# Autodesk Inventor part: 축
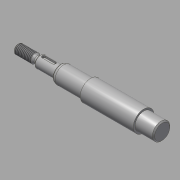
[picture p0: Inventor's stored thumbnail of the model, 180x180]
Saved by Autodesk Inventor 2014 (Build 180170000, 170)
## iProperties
Created: 2015-11
Part Number: 축
Material: 강철, 연강
Document SubType Name: Modeling
Designer: mduedu
Density: 1 g/cm^3
Appearance: 강철
Author: mduedu
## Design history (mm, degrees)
sketch "스케치1"
  geometry: L1 (-86, 0)-(86, 0); L2 (-86, 0)-(-86, 4); L3 (-86, 4)-(-70.732, 4); L4 (-70.732, 4)-(-69, 3); L5 (-69, 3)-(-67, 3); L6 (-67, 3)-(-67, 5); L7 (-67, 5)-(-49, 5); L8 (-49, 5)-(-49, 6.55); L9 (-47.355, 7.5)-(-23, 7.5); L10 (-23, 7.5)-(-23, 9); L11 (0, 0)-(0, 9); L12 (86, 4)-(70.732, 4); L13 (70.732, 4)-(69, 3); L14 (69, 3)-(67, 3); L15 (67, 3)-(67, 5); L16 (67, 5)-(49, 5); L17 (23, 7.5)-(23, 9); L18 (86, 0)-(86, 4); L19 (-23, 9)-(23, 9); L20 (-49, 6.55)-(-47.355, 7.5); L21 (47.355, 7.5)-(23, 7.5); L22 (49, 6.55)-(47.355, 7.5); L23 (49, 5)-(49, 6.55); 1 further point
  constraints: 46 end point, 10 symmetric about line, 6 perpendicular, 5 parallel, 2 midpoint, 1 coincident, 1 horizontal
  dimensions: "d0" = 172 distance of L1.start L1.end (derived); "d1" = 8 diameter of L3 L1; "d2" = 30 deg angle of L4 L5; "d3" = 6 diameter of L5 L1; "d4" = 10 diameter of L7 L1; "d5" = 15 diameter of L9 L1; "d6" = 18 diameter of L19 L1; "d8" = 18 distance of L6.end L7.end; "d9" = 46 distance of L10.end L17.end; "d10" = 2 distance of L4.end L5.end; "d11" = 17 distance from line of L4.end L2; "d16" = 13.1 diameter of L8.end L1; "d17" = 30 deg angle of L20 L9; "d18" = 26 distance between parallel lines of L10 L8
revolve "회전1" sketch "스케치1" stored, may be unused: angle "d12" = 90 deg
chamfer "모따기1" distance "d13" = 1; stored, may be unused: second distance "d14" = 2, angle "d15" = 45 deg
fillet "모깎기1" dims "d19" = 4, "d20" = 0.5
node "작업 평면1"
sketch "스케치2" dims "d23" = 12
  geometry: L1 (-5.5, 1.5)-(3.5, 1.5); L2 (3.5, 1.5)-(3.5, -1.5); L3 (3.5, -1.5)-(-5.5, -1.5); L4 (-5.5, -1.5)-(-5.5, 1.5); L5 (-9, -4)-(-9, 4) reference; 3 further points
  constraints: 8 end point, 2 midpoint, 2 parallel, 2 vertical alignment, 1 horizontal, 1 perpendicular, 4 other
  dimensions: "d21" = 3 distance between parallel lines of L3 L1; "d24" = 2 dimension on L5
extrude "돌출1" cut sketch "스케치2" distance "d25" = 1.8; taper "d26" = 0 deg
feature "스레드1" dims "d27" = 10, "d28" = 0
feature "스레드2" dims "d29" = 10, "d30" = 0
chamfer "모따기2" distance "d31" = 1; stored, may be unused: second distance "d32" = 2, angle "d33" = 45 deg
node "작업 평면2"
sketch "스케치3"
  geometry: C1 r 7.5 at (0, 0) reference; 1 further point
extrude "돌출2" cut sketch "스케치3" stored distance "d36" = 10; taper "d37" = 0 deg
chamfer "모따기3" distance "d38" = 1; stored, may be unused: second distance "d39" = 2, angle "d40" = 45 deg
node "솔리드1"
mirror "대칭1"
node "절단 모서리 투영1"
other parameters: "d35" = 16
